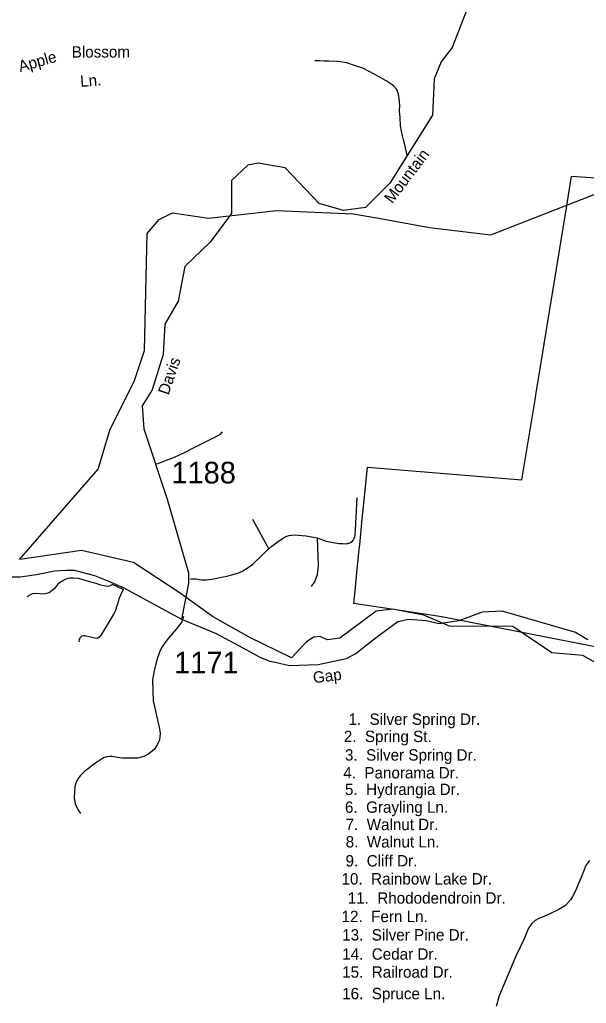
# Model space of a CAD drawing. Extents: x 884530 to 1028605, y 526725 to 653634.
# Drawn here: x 943383 to 946654, y 583000 to 588671 of the extents above; entities that cross this region are included whole.
import ezdxf

# ---------------------------------------------------------------- set-up
doc = ezdxf.new("R2010")
doc.units = 0
for name, color, linetype in [('Exist Boundary Political City Limit New', 7, 'Continuous'), ('Exist Hydrographic Creek Single Shore', 7, 'Continuous'), ('Exist Road Non-System Type 51', 7, 'Continuous'), ('Exist Road Non-System Type 51 Label', 7, 'Continuous'), ('Exist Road Secondary Type 51 Attributed', 7, 'Continuous'), ('Exist Road Secondary Type 51 Label', 7, 'Continuous'), ('Exist Road Secondary Type 51 Number Label', 7, 'Continuous'), ('Map Preparation Boundary City Limit Buffer Line', 7, 'Continuous')]:
    doc.layers.add(name, color=color, linetype=linetype)

msp = doc.modelspace()

# ---------------------------------------------------------------- linework, layer by layer
at = {"layer": 'Exist Boundary Political City Limit New'}
msp.add_lwpolyline([(947009.8, 584995.8), (945819.6, 585228.2), (945568.4, 585266), (945312.4, 585305.4), (945319.4, 585376.9), (945331.9, 585502.7), (945343.1, 585616.1), (945345.7, 585642.1), (945360.4, 585790.8), (945373.1, 585920.2), (945390.1, 586091.2), (946281.4, 586017.6), (946358.1, 586479.2), (946364.7, 586518.9), (946538.8, 587586.2), (946568.5, 587768.2), (946821, 587750.2)], dxfattribs=at)
at = {"layer": 'Exist Hydrographic Creek Single Shore'}
for points in [[(943383.1, 585559.3), (943837, 586078.8), (943903.5, 586303.9), (944047.1, 586589.8), (944103.6, 586762.6), (944119.4, 587438.3), (944188.9, 587519), (944265.3, 587556.8), (944472.7, 587526.4), (944866.4, 587571), (945307.5, 587552.2), (945444.7, 587529.1), (945748.8, 587472.5), (946102.4, 587430), (947042.9, 587798)], [(947206, 584682), (946633.7, 585005.3), (946454.3, 585021.1), (946229.3, 585171.2), (945864.4, 585175), (945716.5, 585237), (945535.6, 585271.9), (945440.6, 585261.1), (945230.4, 585104), (945158.4, 585095.2), (945116.9, 585114.9), (945079.4, 585111), (945036, 585081.3), (944953.1, 584991.9), (944708.3, 585110.4), (944496.1, 585230.4), (944309.5, 585363.8), (944041.1, 585541.5), (943741, 585610.6), (943383.7, 585559.3)]]:
    msp.add_lwpolyline(points, dxfattribs=at)
at = {"layer": 'Exist Road Non-System Type 51'}
for p, q in [((944820.6, 585620), (944729.4, 585788.9)), ((943981.4, 585386), (943919.2, 585415.1))]:
    msp.add_line(p, q, dxfattribs=at)
for points in [[(945620, 587889), (945606.6, 587950), (945598.7, 587978), (945593.5, 588001), (945587.5, 588027.4), (945581.8, 588059.4), (945578.6, 588105.1), (945576.4, 588145), (945577.1, 588176.8), (945573.1, 588214), (945569.6, 588241.8), (945559.2, 588267.9), (945541.8, 588288.7), (945527.8, 588299.4), (945498.3, 588318.3), (945455, 588342.6), (945401, 588372.2), (945364.5, 588391.3), (945343.7, 588396.5), (945316, 588406.9), (945270.6, 588422), (945219, 588428.9), (945167.2, 588431.3), (945140.2, 588432.1), (945113.1, 588432.7), (945086, 588433.3)], [(944174.2, 586109.9), (944277, 586149.1), (944335, 586176.1), (944397.9, 586208.2), (944528.7, 586273), (944543.3, 586281.6), (944553.7, 586294.5)], [(945100, 585684.3), (945151.9, 585664.8), (945225.1, 585651.3), (945247.6, 585650.1), (945262.5, 585649.5), (945272.5, 585650.7), (945280, 585651.3), (945292.4, 585656.9), (945302.3, 585663.1), (945306.1, 585667.5), (945311, 585673.7), (945314.1, 585680.5), (945317.9, 585688), (945319.7, 585699.2), (945322.3, 585729.7), (945330.9, 585915.1)], [(944820.6, 585620), (944838.8, 585635.8), (944869.8, 585658.9), (944899.7, 585678.7), (944925.9, 585692.9), (944939.5, 585696.7), (944951.4, 585699.2), (944967.6, 585699.8), (945014.5, 585697.3), (945036, 585694.3), (945056.7, 585690.3), (945079.1, 585687.5), (945100, 585684.3)], [(945100, 585684.3), (945105.1, 585574.6), (945106.3, 585527.5), (945104.4, 585503.2), (945100, 585472), (945087, 585432.9), (945065.9, 585402.4)], [(944369.9, 585446.9), (944399.8, 585446.9), (944433, 585441.6), (944461.3, 585441.7), (944492.7, 585445.1), (944558, 585457.6), (944578.7, 585463.3), (944608.5, 585469.9), (944641.5, 585479.7), (944664.8, 585489.7), (944707.6, 585516.4), (944729, 585532.4), (944748.2, 585550.6), (944772, 585571), (944796.3, 585597.1), (944815.1, 585615.2), (944820.6, 585620)], [(943919.2, 585415.1), (943905.6, 585405.7), (943891.9, 585402.1), (943868.8, 585405.7), (943851.6, 585411.4), (943824.9, 585420.1), (943780.2, 585432.3), (943725.6, 585448.2), (943691.7, 585451.7), (943672.2, 585451.1), (943650.7, 585446), (943624.8, 585432.3), (943603.9, 585415.8), (943583, 585389.1), (943563.5, 585373.1), (943552.8, 585366.1), (943523.8, 585358.1), (943475.1, 585362.3), (943458.5, 585361.1), (943447.6, 585357.4), (943435.4, 585348.1), (943426.1, 585341.6)], [(943981.4, 585386), (943956.2, 585332.1), (943949.1, 585307), (943941.9, 585285.4), (943936.5, 585264.8), (943929.3, 585249.9), (943853, 585123.5), (943842.2, 585111.3), (943834.1, 585105), (943824.4, 585103.6), (943758.8, 585118.5), (943749.8, 585118.5), (943742.6, 585115.8), (943730, 585105), (943725.7, 585095.1), (943726.5, 585083.4)], [(944328.6, 585229.4), (944319, 585198.4), (944285.9, 585157.5), (944241.9, 585104.4), (944220.3, 585077.4), (944202.6, 585049.6), (944190.2, 585024.9), (944174.8, 584979.5), (944159.2, 584915.8), (944150.9, 584864.6), (944153.4, 584744.5), (944188.8, 584592), (944194.1, 584556.4), (944190.2, 584517.1), (944177.9, 584490), (944159.8, 584463.5), (944128, 584437.5), (944100.1, 584423), (944063.9, 584413.9), (944011.4, 584412.9), (943975.2, 584413), (943949, 584416.8), (943915.8, 584422.3), (943902.7, 584423), (943888.7, 584421.6), (943868.2, 584415.3), (943820.3, 584383.7), (943757.2, 584337), (943733.1, 584312.1), (943724, 584301.2), (943715.5, 584286.6), (943707.8, 584269.6), (943702.4, 584249.6), (943699.3, 584218.8), (943698.6, 584185.6), (943703.2, 584149.5), (943719.4, 584117.8), (943735.5, 584093.9)], [(946672.5, 583823.7), (946650.9, 583794), (946637.4, 583760.3)], [(946637.4, 583760.3), (946623.3, 583724.7), (946608.2, 583689.6), (946593.7, 583652.6), (946573.9, 583615.8), (946562, 583595.8), (946533, 583564.5), (946498.6, 583543.3), (946446.1, 583518), (946408.8, 583499.5), (946380.5, 583489.1), (946358.6, 583476.6), (946336.8, 583458.5), (946318.5, 583428.4), (946294.8, 583371.4), (946247.3, 583271.6), (946190.3, 583138.7), (946149.8, 583042.4), (946132.9, 582982.2)]]:
    msp.add_lwpolyline(points, dxfattribs=at)
at = {"layer": 'Exist Road Secondary Type 51 Attributed'}
for points in [[(945975.8, 588758), (945878.5, 588509.7), (945815.2, 588427), (945776.3, 588329.6), (945766.6, 588120.3), (945519.7, 587728.6), (945378.6, 587587.4), (945252.1, 587569.9), (945111, 587611.8), (944914.8, 587816.1), (944760, 587843.9), (944700.5, 587832), (944605.1, 587743.2), (944605.1, 587553.3), (944483.5, 587387.8), (944337.6, 587246.7), (944298.7, 587047.1), (944220.8, 586915.6), (944211.1, 586740.4), (944147.8, 586535.9), (944089.5, 586443.4), (944099.2, 586312), (944235.4, 585906), (944357, 585482.4), (944357, 585419.2), (944317.4, 585215.2)], [(943122.9, 585483.6), (943164.5, 585473.3), (943293.4, 585459.4), (943386.6, 585458.4), (943480.7, 585472.1), (943583.9, 585493.7), (943654.5, 585497.3), (943698.5, 585496.6), (943815, 585466.3), (943892, 585434.7), (943984.7, 585395.2), (944317.4, 585215.2)], [(944317.4, 585215.2), (944516.7, 585131.9), (944670.9, 585048.7), (944772.9, 584994.1), (944827.9, 584972), (944857.9, 584966.2), (944941.1, 584947.9), (945106.3, 584953.8), (945268.9, 584988.5), (945324.2, 585016.2), (945371.6, 585055.7), (945458.4, 585122.8), (945566.4, 585200.6), (945628.2, 585213.7), (945728.9, 585205.8), (945802.9, 585189.4), (945919.1, 585207.2), (946054.6, 585257.1), (946166.2, 585262.1), (946591.6, 585139.7), (946663.1, 585096.3)]]:
    msp.add_lwpolyline(points, dxfattribs=at)
at = {"layer": 'Map Preparation Boundary City Limit Buffer Line'}
msp.add_lwpolyline([(947009.8, 584995.8), (945819.6, 585228.2), (945568.4, 585266), (945312.4, 585305.4), (945319.4, 585376.9), (945331.9, 585502.7), (945343.1, 585616.1), (945345.7, 585642.1), (945360.4, 585790.8), (945373.1, 585920.2), (945390.1, 586091.2), (946281.4, 586017.6), (946358.1, 586479.2), (946364.7, 586518.9), (946538.8, 587586.2), (946568.5, 587768.2), (946821, 587750.2)], dxfattribs=at)

# ---------------------------------------------------------------- texts
at = {"layer": 'Exist Road Non-System Type 51 Label'}
for s, rotation, p in [('Apple', 15.8741, (943386.7, 588367.8)), ('Blossom', 0.1243, (943683.8, 588451.9)), ('Ln.', 4.6926, (943735.4, 588282.4))]:
    msp.add_text(s, height=65.62, rotation=rotation, dxfattribs=at).set_placement(p)
for s, p in [('1.  Silver Spring Dr.', (945281, 584605)), ('2.  Spring St.', (945254, 584506)), ('3.  Silver Spring Dr.', (945260.8, 584399)), ('4.  Panorama Dr.', (945250.8, 584296.3)), ('5.  Hydrangia Dr.', (945260.8, 584200.7)), ('6.  Grayling Ln.', (945260.8, 584098)), ('7.  Walnut Dr.', (945264.2, 583998)), ('8.  Walnut Ln.', (945264.9, 583898.1)), ('9.  Cliff Dr.', (945264.1, 583788.7)), ('10.  Rainbow Lake Dr.', (945240.9, 583684.7)), ('11.  Rhododendroin Dr.', (945276.5, 583574.2)), ('12.  Fern Ln.', (945241.2, 583467.9)), ('13.  Silver Pine Dr.', (945244.7, 583361.6)), ('14.  Cedar Dr.', (945244.7, 583251.1)), ('15.  Railroad Dr.', (945244.7, 583147.5)), ('16.  Spruce Ln.', (945244.7, 583023.1))]:
    msp.add_text(s, height=65.617, dxfattribs=at).set_placement(p)
at = {"layer": 'Exist Road Secondary Type 51 Label'}
for s, rotation, p in [('Mountain', 52.8301, (945533.8, 587606.2)), ('Davis', 71.059, (944242.1, 586502.8)), ('Gap', 7.2758, (945080.5, 584844.5))]:
    msp.add_text(s, height=65.62, rotation=rotation, dxfattribs=at).set_placement(p)
at = {"layer": 'Exist Road Secondary Type 51 Number Label'}
for s, p in [('1188', (944259.4, 585996.8)), ('1171', (944274.9, 584901.5))]:
    msp.add_text(s, height=125, dxfattribs=at).set_placement(p)

doc.saveas('drawing.dxf')
